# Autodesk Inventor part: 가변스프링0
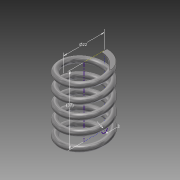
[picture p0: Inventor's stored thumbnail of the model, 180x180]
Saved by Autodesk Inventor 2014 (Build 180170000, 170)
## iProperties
Created: 2015-02
Part Number: 가변스프링0
Material: 강철, 탄소
Document SubType Name: Modeling
Designer: basic
Density: 7.87 g/cm^3
Appearance: 반연마
Mass: 18.8932 g
Surface Area: 32.5308 cm^2
Volume: 2.40066 cm^3
Author: basic
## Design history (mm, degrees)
sketch "스케치1"
  geometry: L1 (0, 0)-(11, 0); L2 (11, 0)-(11, 37); L3 (11, 37)-(0, 37); L4 (0, 37)-(0, 0); C1 r 1.5 at (11, 0)
  constraints: 8 end point, 2 parallel, 1 centre point, 1 coincident, 1 horizontal, 1 perpendicular
  dimensions: "d0" = 22 diameter of L2 L4; "d1" = 37 distance of L3.end L1.start (derived); "d2" = 3 diameter of C1
feature "코일1" sketch "스케치1" pitch "d3" = 10; turns "d5" = 5; dims "d4" = 37 (= d1), "d6" = 0, angle "d7" = 90 deg, angle "d8" = 90 deg, "d9" = 0, "d10" = 0
sketch "스케치2"
  geometry: L1 (0, 12.5)-(0, 9.5) reference; L2 (0, 12.5)-(0, 9.5) reference; 1 further point
  constraints: 2 vertical alignment
extrude "돌출1" cut sketch "스케치2" stored distance "d11" = 10; taper "d12" = 0 deg
node "작업 평면1"
sketch "스케치3"
  geometry: L1 (1.5, 0)-(-1.5, 0) reference; 1 further point
  constraints: 1 horizontal alignment
extrude "돌출2" cut sketch "스케치3" stored distance "d14" = 10; taper "d15" = 0 deg
node "솔리드1"
node "절단 모서리 투영1"
node "절단 모서리 투영2"
node "절단 모서리 투영3"
other parameters: "d13" = 0
